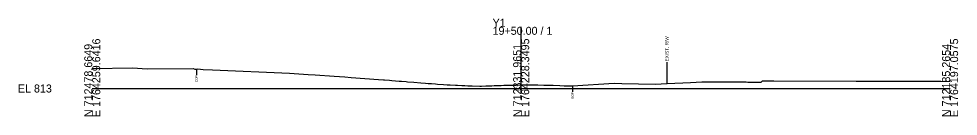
# Model space of a CAD drawing. Extents: x -26 to 1303, y -10 to 9524.
# Drawn here: x -25.7 to 302.8, y 9490.3 to 9524.4 of the extents above; entities that cross this region are included whole.
import ezdxf

# ---------------------------------------------------------------- set-up
doc = ezdxf.new("R2010")
doc.units = 0
for name, color, linetype in [('Default', 7, 'Continuous'), ('Exist Cross Section Cell', 7, 'Continuous'), ('Exist XS Center Line Elevation Label', 7, 'Continuous'), ('Exist XS Ground Line', 7, 'Continuous'), ('Old_Level_10', 7, 'Continuous')]:
    doc.layers.add(name, color=color, linetype=linetype)

msp = doc.modelspace()

# ---------------------------------------------------------------- linework, layer by layer
at = {"layer": 'Exist Cross Section Cell'}
for p, q in [((150, 9500), (150, 9521.58)), ((0, 9500), (150, 9500)), ((150, 9500), (300, 9500))]:
    msp.add_line(p, q, dxfattribs=at)
at = {"layer": 'Exist XS Ground Line'}
msp.add_lwpolyline([(0, 9506.97), (14.05, 9507.19), (19.19, 9506.9), (35.32, 9506.96), (35.93, 9506.73), (36.41, 9506.72), (36.93, 9506.86), (38.82, 9506.62), (42.06, 9506.48), (68.93, 9505.35), (75.46, 9504.9), (77.9, 9504.73), (84.62, 9504.28), (88.38, 9504.03), (90.58, 9503.85), (100.14, 9503.19), (101.81, 9503.06), (102.16, 9503.03), (103.91, 9502.88), (104.72, 9502.8), (106.02, 9502.69), (107.28, 9502.59), (108.13, 9502.51), (109.83, 9502.39), (110.24, 9502.36), (112.46, 9502.17), (114.94, 9501.99), (116.56, 9501.87), (117.5, 9501.79), (118.66, 9501.7), (120.06, 9501.58), (120.77, 9501.52), (122.88, 9501.37), (124.11, 9501.29), (125.17, 9501.23), (127.09, 9501.16), (127.73, 9501.12), (129.2, 9501.05), (130.28, 9501.01), (131.3, 9500.98), (132.84, 9500.94), (135.52, 9500.85), (136.1, 9500.87), (137.62, 9500.91), (137.95, 9500.93), (139.73, 9500.96), (140.51, 9501), (141.84, 9501.07), (143.06, 9501.09), (143.94, 9501.11), (145.62, 9501.17), (146.05, 9501.18), (148.18, 9501.21), (150.27, 9501.25), (150.73, 9501.26), (152.37, 9501.24), (153.29, 9501.23), (154.48, 9501.25), (155.84, 9501.24), (157.95, 9501.22), (158.69, 9501.21), (161.17, 9501.18), (163.51, 9501.1), (165.01, 9500.99), (166.07, 9500.92), (167.99, 9500.92), (182.55, 9501.81), (185.22, 9501.79), (196.81, 9501.51), (201.02, 9501.77), (209.23, 9502.15), (213.23, 9502.29), (222.61, 9502.29), (228.72, 9502.28), (229.26, 9502.27), (233.94, 9502.19), (234.36, 9502.69), (238.36, 9502.69), (267.15, 9502.57), (269.39, 9502.56), (269.91, 9502.56), (276.47, 9502.53), (290.74, 9502.54), (292.9, 9502.54), (296.73, 9502.52), (300, 9502.42)], dxfattribs=at)
at = {"layer": 'Old_Level_10'}
for p, q in [((200.95, 9509.16), (200.95, 9501.76)), ((36.41, 9506.72), (36.41, 9504.67)), ((167.99, 9500.92), (167.99, 9498.87))]:
    msp.add_line(p, q, dxfattribs=at)

# ---------------------------------------------------------------- texts
at = {"layer": 'Default'}
msp.add_text('-', height=0.0001, dxfattribs=at).set_placement((0, 9500))
at = {"layer": 'Exist Cross Section Cell'}
for s, p in [('Y1', (140, 9521.58)), ('19+50.00 / 1', (140, 9518.78)), ('EL 813', (-26, 9498.6))]:
    msp.add_text(s, height=2.8, dxfattribs=at).set_placement(p)
for s, p in [('N 712478.6649', (0, 9490)), ('E 1764259.6416', (2.8, 9490)), ('N 712331.9651', (150, 9490)), ('E 1764228.3495', (152.8, 9490)), ('N 712185.2654', (300, 9490)), ('E 1764197.0575', (302.8, 9490))]:
    msp.add_text(s, height=2.8, rotation=90, dxfattribs=at).set_placement(p)
at = {"layer": 'Exist XS Center Line Elevation Label'}
msp.add_text('814.25', height=1, dxfattribs=at).set_placement((147.99, 9499.25))
at = {"layer": 'Old_Level_10'}
for s, height, p in [('EXIST. R/W', 1.181, (201.54, 9509.47)), ('EOP', 0.787, (36.81, 9502.27)), ('EOP', 0.787, (168.38, 9496.47))]:
    msp.add_text(s, height=height, rotation=90, dxfattribs=at).set_placement(p)

doc.saveas('drawing.dxf')
